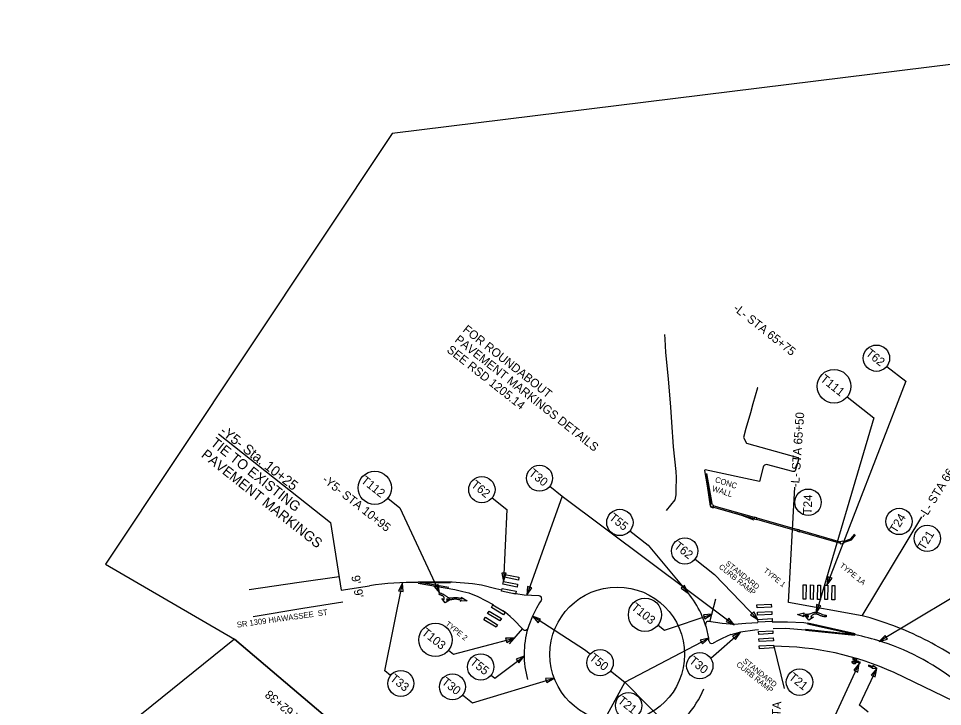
# Model space of a CAD drawing. Extents: x 553958 to 562499, y 493978 to 516388.
# Drawn here: x 557275 to 557920, y 506887 to 507367 of the extents above; entities that cross this region are included whole.
import ezdxf

# ---------------------------------------------------------------- set-up
doc = ezdxf.new("R2010")
doc.units = 0
for name, color, linetype in [('Exist Horizontal Alignment', 7, 'Continuous'), ('Prop Approach Slab', 7, 'Continuous'), ('Prop Conc 4in Sidewalk', 7, 'Continuous'), ('Prop Dimension Text', 7, 'Continuous'), ('Prop EOT', 7, 'Continuous'), ('Prop EOT Dash', 7, 'Continuous'), ('Prop Erosion Rip Rap Class II Label', 7, 'Continuous'), ('Prop Horizontal Alignment Tick Small', 7, 'Continuous'), ('Prop SS Cut Line', 7, 'Continuous'), ('Prop SS Fill Line', 7, 'Continuous'), ('Prop Superelevation Label', 7, 'Continuous'), ('Prop Terminator CELL', 7, 'Continuous'), ('Raster_Level_0', 7, 'Continuous'), ('Scratch_Level_0', 7, 'Continuous'), ('Scratch_Level_3', 7, 'Continuous'), ('Scratch_Level_4', 7, 'Continuous'), ('Sheet Plan CELL', 7, 'Continuous'), ('Sheet Plot Border Inside CELL', 7, 'Continuous'), ('Sheet Plot Border Outside CELL', 7, 'Continuous')]:
    doc.layers.add(name, color=color, linetype=linetype)

msp = doc.modelspace()

# ---------------------------------------------------------------- linework, layer by layer
at = {"layer": 'Exist Horizontal Alignment'}
msp.add_lwpolyline([(557818.42, 506950.87), (557823.07, 506952.06), (557822.35, 506951.31), (557823.12, 506951.27), (557823.88, 506951.23), (557824.91, 506951.19), (557825.53, 506951.19), (557826.08, 506951.22), (557826.62, 506951.3), (557827, 506951.39), (557827.65, 506951.6), (557827.79, 506951.64), (557828.81, 506952.05), (557829.42, 506952.23), (557829.99, 506952.35), (557830.52, 506952.42), (557831.17, 506952.45), (557831.88, 506952.4), (557832.38, 506952.32), (557832.7, 506952.25), (557833.32, 506952.06), (557833.92, 506951.83), (557834.52, 506951.56), (557834.96, 506951.34), (557835.34, 506951.12), (557835.57, 506950.99), (557836, 506950.84), (557836.74, 506950.65), (557837.4, 506950.54), (557837.99, 506950.49), (557838.43, 506950.47), (557838.37, 506949.25), (557837.74, 506949.29), (557837.09, 506949.36), (557836.45, 506949.45), (557835.96, 506949.54), (557835.33, 506949.71), (557834.87, 506949.86), (557834.39, 506950.07), (557834, 506950.3), (557833.58, 506950.52), (557832.95, 506950.8), (557832.4, 506951), (557831.88, 506951.13), (557831.37, 506951.19), (557830.74, 506951.19), (557830.15, 506951.11), (557829.58, 506950.96), (557829.11, 506950.73), (557828.7, 506950.5), (557828.41, 506950.28), (557828.12, 506949.98), (557827.97, 506949.74), (557827.88, 506949.51), (557827.78, 506949.16), (557827.74, 506948.95), (557829.55, 506949.12), (557826.29, 506946.99), (557824.14, 506949.68), (557825.96, 506949.06), (557825.98, 506949.33), (557826.03, 506949.56), (557826.1, 506949.79), (557826.19, 506949.99), (557825.81, 506949.97), (557825.14, 506949.95), (557824.62, 506949.96), (557824.08, 506949.99), (557823.35, 506950.03), (557822.57, 506950.07), (557822.24, 506950.08), (557822.92, 506949.2)], close=True, dxfattribs=at)
msp.add_circle((557692.58, 506923.08), 47, dxfattribs=at)
at = {"layer": 'Prop Approach Slab'}
for p, q in [((557812.07, 506959.32), (557816.54, 507039.8)), ((557863.49, 506950.03), (557905.28, 507018.99)), ((557801.82, 506928.72), (557809.07, 506899.33))]:
    msp.add_line(p, q, dxfattribs=at)
for points in [[(557414.13, 507077.08), (557492.49, 507015.12), (557499.79, 506967.96)], [(557721.09, 506943.52), (557725.53, 506940.01), (557758.76, 506951.13)], [(557687.87, 506911.55), (557697.91, 506903.62), (557730.67, 506870.51)]]:
    msp.add_lwpolyline(points, dxfattribs=at)
msp.add_lwpolyline([(557753.76, 506947.82), (557758.76, 506951.13), (557752.77, 506950.77)], close=True, dxfattribs=at)
for centre, radius in [((557711.98, 506950.73), 11.62), ((557680.64, 506917.27), 9.22), ((557750.26, 506915.16), 9.19), ((557700.51, 506887.33), 9.19)]:
    msp.add_circle(centre, radius, dxfattribs=at)
at = {"layer": 'Prop Dimension Text'}
for p, q in [((557754.15, 507049.33), (557757.8, 507028.18)), ((557755, 507049.36), (557758.71, 507028.36)), ((557759.84, 507025.86), (557788.08, 507017.85)), ((557760.05, 507026.79), (557788.2, 507018.72)), ((557760.05, 507026.79), (557788.2, 507018.72)), ((557789.79, 507017.42), (557818.21, 507009.26)), ((557790.07, 507018.29), (557818.46, 507010.18)), ((557819.98, 507008.83), (557848.46, 507000.62)), ((557820.24, 507009.72), (557848.2, 507001.71))]:
    msp.add_line(p, q, dxfattribs=at)
for points in [[(557757.42, 507027.9), (557757.7, 507026.01), (557759.48, 507025.43), (557759.94, 507027.06), (557759.12, 507027.18), (557758.98, 507028.19), (557757.42, 507027.9)], [(557788.18, 507017.65), (557789.72, 507017.27), (557790.07, 507018.37), (557788.45, 507018.82), (557788.18, 507017.65)], [(557818.33, 507009.1), (557819.78, 507008.66), (557820.11, 507009.81), (557818.66, 507010.22), (557818.33, 507009.1)], [(557850.26, 507001.8), (557855.79, 507003.59), (557858.43, 507007.01)], [(557850.48, 507001.12), (557856.23, 507002.99), (557858.97, 507006.54)], [(557848.33, 507001.81), (557849.99, 507002.22), (557850.45, 507000.51), (557848.8, 507000.01), (557848.33, 507001.81)]]:
    msp.add_lwpolyline(points, dxfattribs=at)
at = {"layer": 'Prop EOT'}
msp.add_line((557863.49, 506950.03), (557812.08, 506959.33), dxfattribs=at)
at = {"layer": 'Prop EOT Dash'}
for p, q in [((557553.64, 506972.75), (557579.31, 506968.43)), ((557553.67, 506973.75), (557577.3, 506973.77)), ((557823.99, 506940.04), (557858.38, 506936.37)), ((557858.61, 506937.35), (557825.56, 506944.81))]:
    msp.add_line(p, q, dxfattribs=at)
at = {"layer": 'Prop Erosion Rip Rap Class II Label'}
for points in [[(557425.46, 506933.59), (557889.73, 506539.36), (558124.72, 506519.69), (558557.87, 506177.2), (558959.56, 506684.21), (558454.57, 507154), (558185.43, 507366.81), (557535.46, 507286.55), (557335.3, 506986.11)], [(557510.24, 505740.54), (557854.59, 506431.05), (557889.73, 506539.36), (557425.46, 506933.59), (557046.6, 506628.46), (556899.98, 506318.25), (557006.57, 505850.3)]]:
    msp.add_lwpolyline(points, close=True, dxfattribs=at)
at = {"layer": 'Prop Horizontal Alignment Tick Small'}
msp.add_lwpolyline([(557870.96, 506915.25), (557871.35, 506914.4), (557868.12, 506915.46), (557867.92, 506914.86), (557871.15, 506913.79), (557870.32, 506913.34), (557873.72, 506913.27)], close=True, dxfattribs=at)
msp.add_lwpolyline([(557870.96, 506915.25), (557871.35, 506914.4), (557868.12, 506915.46), (557867.92, 506914.86), (557871.15, 506913.79), (557870.32, 506913.34), (557873.72, 506913.27)], close=True, dxfattribs=at)
at = {"layer": 'Prop SS Cut Line'}
for centre, radius, start, end in [((557688.46, 506922.12), 69.19, 17.88048, 46.75067), ((557692.58, 506923.08), 65, 163.88408, 195.679), ((557692.71, 506924.09), 65.36, 317.419, 337.48945)]:
    msp.add_arc(centre, radius, start, end, dxfattribs=at)
at = {"layer": 'Prop SS Fill Line'}
for p, q in [((557639.54, 506960.78), (557638.29, 506958.96)), ((557636.16, 506955.32), (557633.4, 506949.63)), ((557638.29, 506958.96), (557636.16, 506955.32)), ((557633.4, 506949.63), (557630.84, 506943.15)), ((557630.84, 506943.15), (557630.12, 506941.21)), ((557754.85, 506941.89), (557754.31, 506943.36)), ((557756.44, 506934.38), (557754.85, 506941.89)), ((557756.63, 506932.51), (557756.44, 506934.38))]:
    msp.add_line(p, q, dxfattribs=at)
msp.add_lwpolyline([(557587.82, 506960.35), (557583.04, 506960.12), (557583.86, 506960.69), (557583.89, 506960.71), (557582.6, 506961.04), (557581.95, 506961.21), (557581.64, 506961.28), (557581.1, 506961.4), (557580.79, 506961.47), (557580.58, 506961.5), (557580.03, 506961.56), (557579.67, 506961.57), (557579.4, 506961.56), (557579.1, 506961.54), (557578.78, 506961.51), (557578.58, 506961.48), (557578.28, 506961.43), (557577.7, 506961.32), (557577.28, 506961.26), (557576.96, 506961.24), (557576.66, 506961.22), (557576.21, 506961.23), (557575.82, 506961.25), (557575.34, 506961.31), (557574.87, 506961.4), (557574.49, 506961.5), (557574.22, 506961.59), (557574.01, 506961.67), (557573.62, 506961.84), (557573.61, 506961.64), (557573.59, 506961.35), (557573.57, 506961.17), (557573.52, 506960.88), (557575.45, 506960.92), (557572.59, 506959.01), (557570.12, 506962.02), (557571.8, 506961.31), (557571.83, 506961.49), (557571.87, 506961.8), (557571.89, 506962.08), (557571.87, 506962.33), (557571.83, 506962.58), (557571.76, 506962.78), (557571.61, 506963.07), (557571.5, 506963.22), (557571.33, 506963.4), (557571.03, 506963.66), (557570.76, 506963.83), (557570.45, 506964), (557570.19, 506964.13), (557569.94, 506964.24), (557569.64, 506964.37), (557569.44, 506964.44), (557569.22, 506964.52), (557568.94, 506964.61), (557568.71, 506964.67), (557568.44, 506964.74), (557568.31, 506964.77), (557568.62, 506965.95), (557569.11, 506965.81), (557569.57, 506965.67), (557569.98, 506965.53), (557570.39, 506965.39), (557570.65, 506965.29), (557570.96, 506965.16), (557571.35, 506964.97), (557571.78, 506964.73), (557572.18, 506964.47), (557572.53, 506964.18), (557572.86, 506963.9), (557573.23, 506963.6), (557573.61, 506963.34), (557574.13, 506963.03), (557574.5, 506962.83), (557574.87, 506962.7), (557575.29, 506962.59), (557575.66, 506962.52), (557576, 506962.48), (557576.24, 506962.47), (557576.62, 506962.49), (557577.31, 506962.54), (557577.94, 506962.61), (557578.5, 506962.69), (557578.85, 506962.75), (557579.04, 506962.77), (557579.51, 506962.81), (557579.94, 506962.81), (557580.44, 506962.76), (557580.96, 506962.68), (557581.52, 506962.58), (557582.01, 506962.46), (557582.66, 506962.29), (557583.69, 506962.03), (557584.24, 506961.89), (557583.76, 506962.88)], close=True, dxfattribs=at)
for centre, start, end in [((557637.89, 506961.91), 325.5134, 63.65166), ((557628.25, 506941.92), 225.68994, 339.42543), ((557756.19, 506944.04), 81.30841, 200.03505), ((557758.62, 506932.71), 185.80909, 297.84547)]:
    msp.add_arc(centre, 2, start, end, dxfattribs=at)
at = {"layer": 'Raster_Level_0'}
msp.add_line((557499.79, 506967.96), (557519.71, 506970.95), dxfattribs=at)
for centre, radius, start, end in [((557550.82, 506763.26), 210, 89.22418, 98.519), ((557819.41, 506749.27), 191.56, 73.30522, 78.75932), ((557827.59, 506776.53), 163.1, 51.69784, 73.30522)]:
    msp.add_arc(centre, radius, start, end, dxfattribs=at)
at = {"layer": 'Scratch_Level_0'}
for points in [[(557498.4, 506977.2), (557470.64, 506973.21), (557435.55, 506968.02)], [(557501.05, 506959.55), (557473.15, 506955.12), (557438.44, 506949.28)]]:
    msp.add_lwpolyline(points, dxfattribs=at)
at = {"layer": 'Scratch_Level_3'}
for points in [[(557726.88, 507023.38), (557732.93, 507031.02), (557733.74, 507034.41), (557733.66, 507037.67), (557733.88, 507046.39), (557733.7, 507050.79), (557731.78, 507067.84), (557730.67, 507085.18), (557729.97, 507095.56), (557728.41, 507115.31), (557726.63, 507133.75), (557726.09, 507143.07), (557725.9, 507146.33)], [(557790.73, 507108.97), (557790.45, 507109.1), (557787.21, 507098.01), (557785.56, 507091.59), (557782.44, 507080.72), (557780.72, 507074.47), (557782.84, 507070.56), (557808.6, 507063.33), (557818.59, 507060.4), (557819.06, 507059.87), (557819.22, 507058.76), (557816.73, 507051.08), (557816.31, 507050.78), (557815.29, 507050.69), (557796.92, 507055.55), (557795.47, 507055.15), (557794.6, 507054.39), (557794.43, 507053.81), (557791.97, 507043.74), (557753.92, 507051.75), (557753.5, 507051.44), (557755.43, 507040.78), (557757.49, 507026.51), (557779.32, 507020.25), (557787.86, 507016.91)]]:
    msp.add_lwpolyline(points, dxfattribs=at)
at = {"layer": 'Scratch_Level_4'}
for p, q in [((557857.56, 506916.81), (557857.62, 506917.04)), ((557857.56, 506916.81), (557857.62, 506917.04)), ((557857.78, 506918.62), (557857.9, 506918.83)), ((557859.53, 506917.42), (557857.78, 506918.62)), ((557857.83, 506917.83), (557857.9, 506918.07)), ((557857.83, 506917.83), (557857.9, 506918.07)), ((557857.92, 506918.82), (557859.56, 506917.69)), ((557858.19, 506919.17), (557858.25, 506919.41)), ((557858.19, 506919.17), (557858.25, 506919.41)), ((557858.47, 506920.19), (557858.53, 506920.43)), ((557858.47, 506920.19), (557858.53, 506920.43)), ((557858.81, 506918.49), (557858.82, 506918.73)), ((557859.46, 506918.46), (557858.81, 506918.49)), ((557858.82, 506918.73), (557859.66, 506918.69)), ((557859.56, 506917.69), (557859.46, 506918.46)), ((557861.17, 506917.09), (557859.53, 506917.42)), ((557859.66, 506918.69), (557859.8, 506917.68)), ((557859.8, 506917.68), (557860.87, 506917.46)), ((557860.12, 506918.62), (557860.42, 506918.54)), ((557860.87, 506917.46), (557860.12, 506918.62)), ((557860.42, 506918.54), (557861.16, 506917.42)), ((557861.16, 506917.42), (557861.17, 506917.09)), ((557861.64, 506916.82), (557861.6, 506916.67)), ((557861.64, 506916.82), (557861.6, 506916.67)), ((557861.89, 506917.76), (557861.86, 506917.61)), ((557861.89, 506917.76), (557861.86, 506917.61))]:
    msp.add_line(p, q, dxfattribs=at)
for points in [[(557623.63, 506974.96), (557613.82, 506976.91), (557614.21, 506978.87), (557624.02, 506976.92)], [(557622.65, 506970.06), (557612.84, 506972.01), (557613.23, 506973.97), (557623.04, 506972.02)], [(557621.67, 506965.15), (557611.87, 506967.1), (557612.26, 506969.06), (557622.06, 506967.11)], [(557822.31, 506961.54), (557822.49, 506971.53), (557824.49, 506971.5), (557824.31, 506961.5)], [(557827.43, 506961.5), (557827.61, 506971.5), (557829.6, 506971.46), (557829.43, 506961.47)], [(557832.43, 506961.41), (557832.6, 506971.41), (557834.6, 506971.38), (557834.43, 506961.38)], [(557837.43, 506961.32), (557837.6, 506971.32), (557839.6, 506971.29), (557839.43, 506961.29)], [(557842.43, 506961.24), (557842.6, 506971.23), (557844.6, 506971.2), (557844.43, 506961.2)], [(557610.69, 506946.43), (557602.14, 506951.62), (557603.18, 506953.33), (557611.73, 506948.14)], [(557613.29, 506950.7), (557604.74, 506955.89), (557605.78, 506957.6), (557614.32, 506952.41)], [(557790.15, 506957.57), (557800.13, 506958.12), (557800.24, 506956.12), (557790.26, 506955.57)], [(557790.48, 506952.46), (557800.47, 506953.01), (557800.58, 506951.01), (557790.59, 506950.46)], [(557608.08, 506942.03), (557599.54, 506947.21), (557600.57, 506948.92), (557609.12, 506943.74)], [(557790.76, 506947.47), (557800.74, 506948.02), (557800.85, 506946.02), (557790.87, 506945.47)], [(557791.24, 506938.98), (557801.22, 506939.53), (557801.33, 506937.54), (557791.35, 506936.98)], [(557791.51, 506933.99), (557801.5, 506934.54), (557801.61, 506932.54), (557791.62, 506931.99)], [(557791.79, 506929), (557801.77, 506929.55), (557801.88, 506927.55), (557791.9, 506927)]]:
    msp.add_lwpolyline(points, close=True, dxfattribs=at)
for radius, start, end in [(0.41, 75.00356, 255.00356), (0.563, 255.00356, 75.00356), (0.563, 255.00356, 75.00356)]:
    msp.add_arc((557861.75, 506917.22), radius, start, end, dxfattribs=at)
for centre, major_axis, ratio, start_param, end_param in [((557858.36, 506919.8), (-1.44, 0.39), 0.435841, 4.712389, 7.853982), ((557857.73, 506917.44), (-1.44, 0.39), 0.435841, 4.712389, 7.853982), ((557857.73, 506917.44), (-1.21, 0.32), 0.325967, 4.712389, 7.853982), ((557858.36, 506919.8), (-1.21, 0.32), 0.325967, 4.712389, 7.853982), ((557857.73, 506917.44), (-1.44, 0.39), 0.435841, 1.570796, 4.712389), ((557857.73, 506917.44), (-1.21, 0.32), 0.325967, 1.570796, 4.712389), ((557858.36, 506919.8), (-1.44, 0.39), 0.435841, 1.570796, 4.712389), ((557858.36, 506919.8), (-1.21, 0.32), 0.325967, 1.570796, 4.712389)]:
    msp.add_ellipse(centre, major_axis=major_axis, ratio=ratio, start_param=start_param, end_param=end_param, dxfattribs=at)
at = {"layer": 'Sheet Plan CELL'}
for points in [[(557880.78, 507124.07), (557893.97, 507113.64), (557839.01, 506971.3)], [(557853.19, 507102.84), (557871.75, 507088.16), (557831.52, 506951.77)], [(557645.51, 507040.36), (557654.19, 507033.49), (557629.53, 506964.46)], [(557645.51, 507040.36), (557654.19, 507033.49), (557774.15, 506943.68)], [(557532.44, 507032.06), (557540.94, 507025.33), (557568.62, 506965.95)], [(557605.29, 507032.31), (557615.56, 507024.19), (557613.23, 506973.97)], [(557701.5, 507009.23), (557714.08, 506999.23), (557742.13, 506965.78)], [(557746.94, 506989.53), (557760.43, 506978.87), (557790.76, 506947.47)], [(557534.38, 506908.44), (557530.28, 506911.68), (557542.68, 506972.86)], [(557931.43, 506957.03), (557925.25, 506961.91), (557875.47, 506932.02)], [(557673.59, 506923.2), (557669.74, 506926.25), (557633.4, 506949.63)], [(557574.81, 506925.96), (557578.35, 506923.16), (557620.66, 506934.35)], [(557687.87, 506911.55), (557697.91, 506903.62), (557756.44, 506934.38)], [(557757.87, 506920.31), (557778.55, 506938.56)], [(557604.54, 506908.62), (557607.19, 506906.52), (557627.6, 506921.85)], [(557844.07, 506859.85), (557837.72, 506865.32), (557861.6, 506916.67)], [(557687.87, 506911.55), (557697.91, 506903.62), (557674.29, 506860.71)], [(557867.83, 506882.81), (557861.78, 506887.6), (557873.72, 506913.27)], [(557584.69, 506894.78), (557591.63, 506889.29), (557648.59, 506906.55)]]:
    msp.add_lwpolyline(points, dxfattribs=at)
for points in [[(557611.95, 506979.83), (557613.23, 506973.97), (557615.05, 506979.69)], [(557543.05, 506966.87), (557542.68, 506972.86), (557540, 506967.49)], [(557839.65, 506977.26), (557839.01, 506971.3), (557842.55, 506976.15)], [(557564.76, 506970.55), (557568.62, 506965.95), (557567.58, 506971.86)], [(557630.02, 506970.44), (557629.53, 506964.46), (557632.95, 506969.39)], [(557737.22, 506969.23), (557742.13, 506965.78), (557739.6, 506971.22)], [(557785.62, 506950.56), (557790.76, 506947.47), (557787.85, 506952.72)], [(557831.67, 506957.84), (557831.52, 506951.77), (557834.69, 506956.95)], [(557639.06, 506947.62), (557633.4, 506949.63), (557637.3, 506945.06)], [(557768.6, 506945.96), (557774.15, 506943.68), (557770.49, 506948.43)], [(557615.46, 506931.37), (557620.66, 506934.35), (557614.66, 506934.37)], [(557752.03, 506930.31), (557756.44, 506934.38), (557750.58, 506933.06)], [(557775.23, 506933.56), (557778.55, 506938.56), (557773.17, 506935.89)], [(557879.64, 506936.33), (557875.47, 506932.02), (557881.23, 506933.67)], [(557623.89, 506917.13), (557627.6, 506921.85), (557622.03, 506919.62)], [(557860.57, 506910.76), (557861.6, 506916.67), (557857.75, 506912.07)], [(557872.68, 506907.36), (557873.72, 506913.27), (557869.86, 506908.67)], [(557643.49, 506903.38), (557648.59, 506906.55), (557642.59, 506906.35)]]:
    msp.add_lwpolyline(points, close=True, dxfattribs=at)
for centre, radius in [((557873.57, 507129.77), 9.19), ((557843.94, 507110.15), 11.78), ((557523.32, 507039.27), 11.62), ((557638.38, 507046), 9.09), ((557598.08, 507038.01), 9.19), ((557825.84, 507029.25), 9.19), ((557694.42, 507015.1), 9.19), ((557889.34, 507015.8), 9.19), ((557909.07, 507004), 9.19), ((557739.73, 506995.24), 9.19), ((557565.7, 506933.17), 11.62), ((557597.33, 506914.32), 9.19), ((557541.48, 506902.82), 9.06), ((557577.56, 506900.42), 9.09), ((557819.85, 506903.68), 9.22)]:
    msp.add_circle(centre, radius, dxfattribs=at)
at = {"layer": 'Sheet Plot Border Inside CELL'}
for p, q in [((557757.36, 506945.69), (557761.54, 506961.93)), ((557626.43, 506941.13), (557617.25, 506930.35)), ((557935.03, 506886.75), (557885.92, 506910.35))]:
    msp.add_line(p, q, dxfattribs=at)
for centre, radius, start, end in [((557806.54, 506733.39), 224, 63.33344, 75.26977), ((557806.54, 506733.39), 224, 51.69784, 63.33344), ((557801.31, 506724.72), 204, 65.52034, 89.8628)]:
    msp.add_arc(centre, radius, start, end, dxfattribs=at)
at = {"layer": 'Sheet Plot Border Outside CELL'}
for p, q in [((557553.65, 506972.74), (557579.31, 506968.43)), ((557553.67, 506973.75), (557577.3, 506973.77)), ((557554.87, 506973.15), (557576.21, 506973.16)), ((557575.1, 506969.75), (557554.87, 506973.15)), ((557577.32, 506973.76), (557591.53, 506972.63)), ((557591.53, 506972.63), (557597.87, 506971.52)), ((557579.29, 506968.44), (557584.79, 506966.97)), ((557584.8, 506966.97), (557589.07, 506966.03)), ((557589.07, 506966.03), (557595.35, 506963.45)), ((557597.88, 506971.52), (557607.92, 506969.13)), ((557607.93, 506969.13), (557612.05, 506968.03)), ((557620.1, 506965.7), (557621.75, 506965.49)), ((557595.33, 506963.46), (557605.91, 506957.96)), ((557621.75, 506965.49), (557627.52, 506964.53)), ((557627.52, 506964.53), (557637.85, 506964.16)), ((557637.85, 506964.16), (557638.78, 506963.7)), ((557614.58, 506952.23), (557612.84, 506953.48)), ((557617.78, 506949.53), (557614.58, 506952.23)), ((557620.7, 506947.04), (557617.78, 506949.53)), ((557626.31, 506941.01), (557620.7, 506947.04)), ((557626.85, 506940.49), (557626.31, 506941.01)), ((557765.87, 506944.59), (557756.49, 506946.02)), ((557774.16, 506943.88), (557765.86, 506944.59)), ((557782.26, 506944.52), (557774.13, 506943.88)), ((557788.64, 506940.04), (557778.55, 506938.56)), ((557790.83, 506945.11), (557782.27, 506944.52)), ((557791.23, 506940.27), (557788.64, 506940.04)), ((557800.87, 506945.71), (557811.47, 506945.85)), ((557810.4, 506941.07), (557801.4, 506941)), ((557823.99, 506940.04), (557810.38, 506941.07)), ((557811.49, 506945.85), (557822.91, 506945.29)), ((557822.91, 506945.29), (557825.56, 506944.81)), ((557858.52, 506936.34), (557823.99, 506940.04)), ((557824.05, 506940.64), (557856.76, 506937.15)), ((557856.76, 506937.15), (557825.42, 506944.22)), ((557825.56, 506944.81), (557858.77, 506937.31)), ((557765.97, 506934.22), (557763.17, 506932.86)), ((557771.86, 506936.83), (557765.97, 506934.22)), ((557778.56, 506938.56), (557771.84, 506936.82)), ((557763.17, 506932.86), (557759.58, 506930.96))]:
    msp.add_line(p, q, dxfattribs=at)

# ---------------------------------------------------------------- texts
at = {"layer": 'Prop Approach Slab'}
for s, height, p in [('-Y5- Sta. 10+25', 7, (557414.66, 507077.75)), ('TIE TO EXISTING', 7, (557408.15, 507069.52)), ('PAVEMENT MARKINGS', 7, (557401.64, 507061.28)), ('T103', 6, (557701.88, 506954.89)), ('T50', 6, (557672.64, 506919.77)), ('T30', 6, (557742.28, 506917.64)), ('T21', 6, (557692.52, 506889.82))]:
    msp.add_text(s, height=height, rotation=321.66667, dxfattribs=at).set_placement(p)
at = {"layer": 'Prop Conc 4in Sidewalk'}
for s, p in [('CURB RAMP', (557763.17, 506983.48)), ('STANDARD ', (557767.79, 506985.87)), ('TYPE 1A', (557847.55, 506984.41)), ('TYPE 1', (557794.36, 506980.85)), ('TYPE 2', (557572.32, 506943.62)), ('CURB RAMP', (557775.33, 506915.37)), ('STANDARD ', (557779.95, 506917.76))]:
    msp.add_text(s, height=3.75, rotation=321.33215, dxfattribs=at).set_placement(p)
at = {"layer": 'Prop EOT'}
for p in [(557506.89, 506977.62), (557508.58, 506968.03)]:
    msp.add_text("9'", height=6, rotation=280.89474, dxfattribs=at).set_placement(p)
at = {"layer": 'Prop Superelevation Label'}
msp.add_text('SR 1309 HIAWASSEE  ST', height=4, rotation=8.00852, dxfattribs=at).set_placement((557427.32, 506941.71))
at = {"layer": 'Prop Terminator CELL'}
for s, p in [('CONC', (557760.52, 507043.34)), ('WALL', (557758.47, 507037.17))]:
    msp.add_text(s, height=4, rotation=342.22243, dxfattribs=at).set_placement(p)
at = {"layer": 'Sheet Plan CELL'}
for s, height, rotation, p in [('-L- STA 65+75', 6, 321.66667, (557773.14, 507163.53)), ('FOR ROUNDABOUT', 6, 321.66667, (557584.27, 507148.76)), ('PAVEMENT MARKINGS DETAILS', 6, 321.66667, (557578.68, 507141.7)), ('SEE RSD 1205.14', 6, 321.66667, (557573.1, 507134.64)), ('T62', 6, 321.66667, (557865.6, 507132.25)), ('T111', 6.072, 321.66667, (557833.86, 507114.24)), ('-L- STA 65+50', 6, 85.95848, (557819.53, 507039.59)), ('-L- STA 66+00', 6, 58.2247, (557907.83, 507017.41)), ('T30', 6, 321.66667, (557630.38, 507048.5)), ('-Y5- STA 10+95', 6, 321.66667, (557486.18, 507044.04)), ('T112', 6, 321.66667, (557513.23, 507043.42)), ('T62', 6, 321.66667, (557590.11, 507040.49)), ('T24', 6, 87.65126, (557828.24, 507020.65)), ('T55', 6, 321.66667, (557686.44, 507017.59)), ('T24', 6, 58.55994, (557887.25, 507007.12)), ('T21', 6, 58.55994, (557906.99, 506995.32)), ('T62', 6, 321.66667, (557731.75, 506997.72)), ('T103', 6, 321.66667, (557555.6, 506937.32)), ('T55', 6, 321.66667, (557589.34, 506916.81)), ('T33', 6, 321.66667, (557533.51, 506905.3)), ('T21', 6, 321.66667, (557811.85, 506906.18)), ('T30', 6, 321.66667, (557569.55, 506902.93)), ('-L- STA 62+38', 6, 140.15551, (557490.11, 506864.97)), ('-L- STA ', 6, 86.67488, (557805.48, 506862.47))]:
    msp.add_text(s, height=height, rotation=rotation, dxfattribs=at).set_placement(p)

doc.saveas('drawing.dxf')
